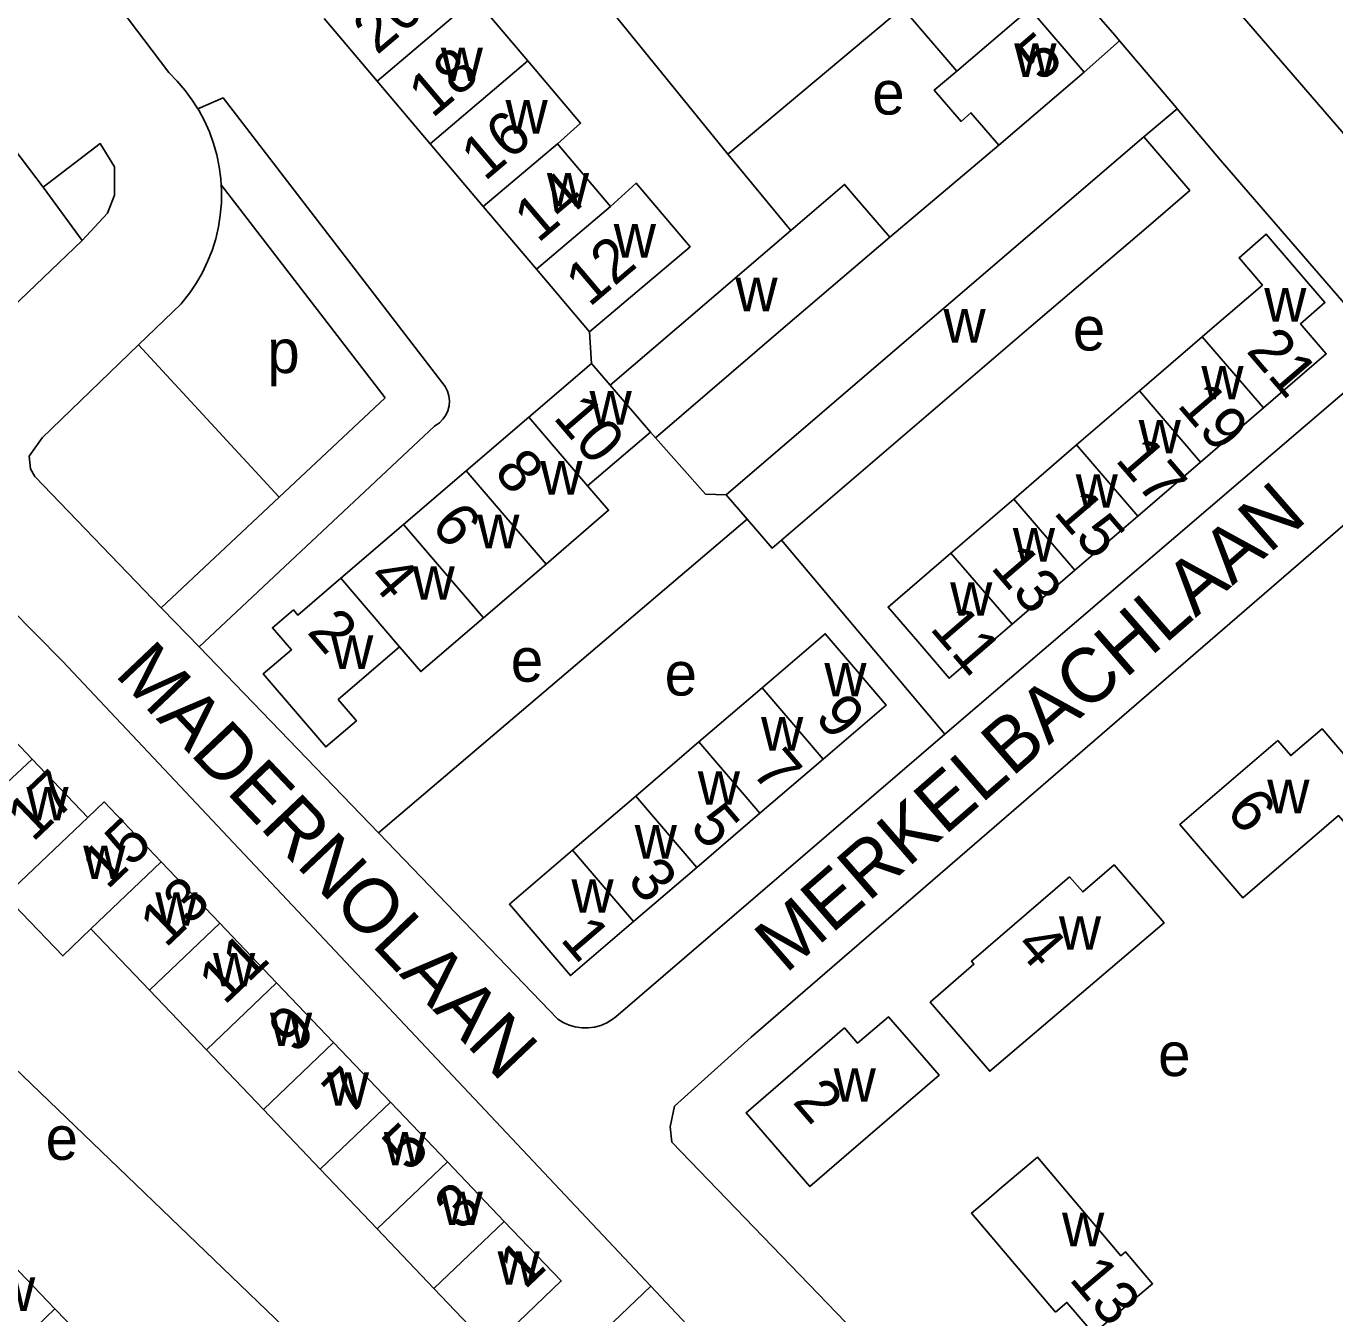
# Model space of a CAD drawing. Extents: x 158848 to 160613, y 385889 to 387762.
# Drawn here: x 160005.9 to 160125.8, y 386409.7 to 386527.7 of the extents above; entities that cross this region are included whole.
import ezdxf

# ---------------------------------------------------------------- set-up
doc = ezdxf.new("R2010")
doc.units = 0
for name, color, linetype in [('BLT_Basislijn', 7, 'Continuous'), ('BLT_Bebouwing', 7, 'Continuous'), ('BLT_Centroide', 7, 'Continuous'), ('BLT_Huisnummer', 7, 'Continuous'), ('BLT_Huisnummer_ tussenligend', 7, 'Continuous'), ('BLT_Onderverdeling_panden', 7, 'Continuous'), ('BLT_Straatnaam', 7, 'Continuous')]:
    doc.layers.add(name, color=color, linetype=linetype)

msp = doc.modelspace()

# ---------------------------------------------------------------- linework, layer by layer
at = {"layer": 'BLT_Basislijn'}
for p, q in [((160018.93, 386523.43), (160006.23, 386540.3)), ((160070.18, 386515.95), (160086.18, 386529.36)), ((160102.84, 386523.47), (160106.06, 386526.36)), ((160111.36, 386520.11), (160108.31, 386517.53)), ((160007.42, 386512.92), (160003.27, 386518.36)), ((160085.01, 386508.36), (160095.01, 386516.77)), ((160070.18, 386515.95), (160075.94, 386508.96)), ((160038.76, 386493.62), (160023.73, 386513.15)), ((160007.42, 386512.92), (160010.99, 386508.05)), ((160010.99, 386508.05), (159994.52, 386492.32)), ((160057.68, 386496.77), (160057.5, 386499.67)), ((160016.16, 386498.47), (160029.05, 386484.51)), ((160038.76, 386493.62), (160029.05, 386484.51)), ((160043.3, 386491.02), (160021.72, 386470.78)), ((160029.05, 386484.51), (160018.24, 386474.37)), ((160038.16, 386453.74), (160071.95, 386482.5)), ((160075.09, 386480.58), (160090.05, 386462.8)), ((160018.24, 386474.37), (160018.35, 386474.25)), ((160021.72, 386470.78), (160018.35, 386474.25)), ((160038.16, 386453.74), (160021.72, 386470.78)), ((160059.91, 386436.87), (160090.05, 386462.8)), ((160038.16, 386453.74), (160054.58, 386436.66)), ((160001.18, 386435.67), (160041.38, 386397.03)), ((160063.11, 386412.2), (160048.57, 386398.28))]:
    msp.add_line(p, q, dxfattribs=at)
for points in [[(160120.89, 386570.12), (160101.88, 386553.46), (160100.45, 386551.77), (160100.03, 386549.96), (160100.67, 386547.91), (160133.83, 386509.51)], [(160050.78, 386539.46), (160051.37, 386539.12), (160070.18, 386515.95)], [(160096.06, 386537.88), (160105.65, 386526.85), (160106.06, 386526.36)], [(160111.36, 386520.11), (160111.3, 386520.19), (160106.06, 386526.36)], [(160018.93, 386523.43), (160019.71, 386522.65), (160020.43, 386521.8), (160021.08, 386520.91), (160021.59, 386520.11)], [(160044.28, 386494.65), (160023.91, 386521.11), (160021.59, 386520.11)], [(160021.59, 386520.11), (160021.68, 386519.98), (160022.2, 386519), (160022.65, 386517.99), (160023.03, 386516.94), (160023.33, 386515.88), (160023.55, 386514.79), (160023.7, 386513.69), (160023.73, 386513.15)], [(160090.05, 386462.8), (160129.22, 386496.31), (160129.31, 386498.66), (160128.99, 386499.61), (160115.32, 386515.4), (160111.36, 386520.11)], [(160010.99, 386508.05), (160013.3, 386510.55), (160013.97, 386512.2), (160013.97, 386514.8), (160012.65, 386516.93), (160007.42, 386512.92)], [(160023.73, 386513.15), (160023.76, 386512.59), (160023.75, 386511.48), (160023.65, 386510.37), (160023.48, 386509.28), (160023.23, 386508.2), (160022.9, 386507.14), (160022.49, 386506.11), (160022.01, 386505.11), (160021.46, 386504.15), (160020.85, 386503.23), (160020.16, 386502.35), (160020.06, 386502.23)], [(160020.06, 386502.23), (160016.16, 386498.47)], [(160016.16, 386498.47), (160007.34, 386489.96), (160006.14, 386488.28), (160006.25, 386487.11), (160006.65, 386486.42), (160018.24, 386474.37)], [(160044.28, 386494.65), (160044.48, 386494.23), (160044.61, 386493.79), (160044.65, 386493.34), (160044.62, 386492.88), (160044.5, 386492.44), (160044.32, 386492.03), (160044.06, 386491.65), (160043.74, 386491.32), (160043.3, 386491.02)], [(160063.53, 386489.95), (160068.13, 386484.8), (160070.03, 386484.74)], [(160083.46, 386406.29), (160065.04, 386425.4), (160064.88, 386426.78), (160065.3, 386428.7), (160072.32, 386435), (160133.52, 386487.91), (160134.87, 386488.67), (160137.1, 386488.79), (160139.96, 386487.11), (160181.86, 386438.35)], [(159975.08, 386460.67), (159994.08, 386479.01), (159996.09, 386479.96), (159998.22, 386479.8), (159999.47, 386479.28), (160009.19, 386469.49), (160063.11, 386412.2)], [(160054.58, 386436.66), (160055.09, 386436.36), (160055.63, 386436.12), (160056.19, 386435.95), (160056.78, 386435.87), (160057.37, 386435.86), (160057.95, 386435.94), (160058.52, 386436.09), (160059.07, 386436.32), (160059.58, 386436.62), (160059.91, 386436.87)], [(160021.79, 386371.56), (160039.4, 386353.42), (160041.49, 386352.9), (160042.58, 386353.01), (160045.16, 386354.66), (160053.07, 386361.02), (160074.23, 386378.29), (160083.27, 386386.2), (160084.09, 386387.66), (160083.81, 386390.16), (160063.11, 386412.2)]]:
    msp.add_lwpolyline(points, dxfattribs=at)
at = {"layer": 'BLT_Bebouwing'}
for p, q in [((160091.15, 386523.55), (160086.18, 386529.36)), ((160102.84, 386523.47), (160097.86, 386529.29)), ((160038.03, 386522.65), (160033.16, 386528.39)), ((160042.9, 386516.9), (160038.03, 386522.65)), ((160095.01, 386516.77), (160102.84, 386523.47)), ((160047.76, 386511.16), (160042.9, 386516.9)), ((160059.42, 386511.17), (160054.55, 386516.91)), ((160052.63, 386505.41), (160047.76, 386511.16)), ((160057.5, 386499.67), (160052.63, 386505.41)), ((160107.9, 386494.25), (160113.66, 386499.21)), ((160057.68, 386496.77), (160051.92, 386491.84)), ((160059.39, 386494.78), (160057.68, 386496.77)), ((160102.14, 386489.3), (160107.9, 386494.25)), ((160113.51, 386487.73), (160119.27, 386492.69)), ((160051.92, 386491.84), (160046.18, 386486.93)), ((160057.31, 386485.54), (160063.08, 386490.47)), ((160063.08, 386490.47), (160063.53, 386489.95)), ((160096.38, 386484.34), (160102.14, 386489.3)), ((160046.18, 386486.93), (160040.44, 386482.01)), ((160107.75, 386482.78), (160113.51, 386487.73)), ((160070.03, 386484.74), (160071.95, 386482.5)), ((160090.62, 386479.39), (160096.38, 386484.34)), ((160040.44, 386482.01), (160034.69, 386477.09)), ((160101.99, 386477.82), (160107.75, 386482.78)), ((160047.77, 386473.45), (160053.51, 386478.38)), ((160096.23, 386472.87), (160101.99, 386477.82)), ((160067.53, 386462.07), (160073.32, 386467.03)), ((160006.41, 386460.5), (160001.14, 386466.02)), ((160061.74, 386457.11), (160067.53, 386462.07)), ((160011.51, 386455.15), (160006.41, 386460.5)), ((160073.12, 386455.54), (160078.91, 386460.49)), ((160055.95, 386452.15), (160061.74, 386457.11)), ((160067.33, 386450.58), (160073.12, 386455.54)), ((160023.6, 386445.46), (160018.23, 386451.09)), ((160061.54, 386445.62), (160067.33, 386450.58)), ((160017.16, 386439.32), (160011.8, 386444.94)), ((160028.82, 386440), (160023.6, 386445.46)), ((160034.03, 386434.53), (160028.82, 386440)), ((160022.38, 386433.85), (160017.16, 386439.32)), ((160027.6, 386428.39), (160022.38, 386433.85)), ((160039.25, 386429.06), (160034.03, 386434.53)), ((160044.47, 386423.59), (160039.25, 386429.06)), ((160032.81, 386422.92), (160027.6, 386428.39)), ((160049.68, 386418.12), (160044.47, 386423.59)), ((160038.03, 386417.45), (160032.81, 386422.92)), ((160043.24, 386411.98), (160038.03, 386417.45)), ((160003.25, 386415.55), (160008.5, 386410.11)), ((160008.5, 386410.11), (160013.75, 386404.68))]:
    msp.add_line(p, q, dxfattribs=at)
for points in [[(160051.83, 386524.52), (160046.94, 386530.29), (160044.82, 386528.4)], [(160054.55, 386516.91), (160056.68, 386518.8), (160051.83, 386524.52)], [(160095.01, 386516.77), (160092.46, 386519.75), (160091.55, 386518.96), (160089.09, 386521.83), (160091.15, 386523.55)], [(160108.31, 386517.53), (160087.84, 386500), (160070.03, 386484.74)], [(160108.31, 386517.53), (160112.51, 386512.63), (160108.72, 386509.37), (160097.77, 386500), (160075.09, 386480.58)], [(160059.42, 386511.17), (160061.77, 386513.3), (160066.71, 386507.47), (160060.87, 386502.52), (160057.5, 386499.67)], [(160075.94, 386508.96), (160080.88, 386513.18), (160081.76, 386512.15), (160085.01, 386508.36)], [(160075.94, 386508.96), (160065.49, 386500), (160059.39, 386494.78)], [(160063.53, 386489.95), (160075.26, 386500), (160085.01, 386508.36)], [(160113.66, 386499.21), (160114.58, 386500), (160119.18, 386503.96), (160117.03, 386506.46), (160119.52, 386508.61), (160124.9, 386502.35), (160122.65, 386500.4), (160123, 386500), (160125.03, 386497.64), (160119.27, 386492.69)], [(160053.51, 386478.38), (160059.24, 386483.32), (160057.31, 386485.54)], [(160071.95, 386482.5), (160073.28, 386480.95), (160074.23, 386479.84), (160075.09, 386480.58)], [(160096.23, 386472.87), (160090.46, 386467.92), (160087.58, 386471.27), (160084.86, 386474.44), (160090.62, 386479.39)], [(160040.09, 386470.79), (160034.47, 386465.96), (160036.13, 386464.02), (160033.32, 386461.62), (160027.58, 386468.31), (160030.17, 386470.52), (160028.43, 386472.54), (160030.35, 386474.18), (160030.75, 386473.71), (160034.69, 386477.09)], [(160040.09, 386470.79), (160042.03, 386468.52), (160047.77, 386473.45)], [(160073.32, 386467.03), (160079.11, 386471.99), (160081.87, 386468.76), (160084.7, 386465.45), (160078.91, 386460.49)], [(160120.59, 386462.21), (160121.77, 386460.83), (160124.64, 386463.29), (160127.89, 386459.5), (160131.35, 386455.46), (160128.29, 386452.83), (160126.15, 386455.32), (160117.37, 386447.79), (160114.44, 386451.21), (160111.61, 386454.52), (160120.59, 386462.21)], [(160018.23, 386451.09), (160013, 386456.57), (160011.51, 386455.15)], [(160055.95, 386452.15), (160054.24, 386450.7), (160050.15, 386447.2), (160055.75, 386440.66), (160061.54, 386445.62)], [(160101.5, 386449.71), (160102.7, 386448.33), (160105.57, 386450.8), (160108.84, 386447.02), (160110.16, 386445.48), (160094.18, 386431.89), (160088.71, 386438.22), (160092.73, 386441.69), (160092.51, 386441.97), (160101.5, 386449.71)], [(160011.8, 386444.94), (160009.21, 386442.46), (160003.96, 386447.95), (160005.34, 386449.27)], [(160081.48, 386424.58), (160089.53, 386431.52), (160088.16, 386433.11), (160084.9, 386436.89), (160082.07, 386434.45), (160080.86, 386435.86), (160071.85, 386428.08), (160077.7, 386421.31), (160081.48, 386424.58)], [(160100.21, 386409.81), (160101.26, 386410.7), (160103.69, 386407.84), (160109.1, 386412.41), (160106.63, 386415.33), (160106.21, 386414.98), (160098.57, 386424.01), (160095.48, 386421.4), (160093.68, 386419.87), (160092.52, 386418.89), (160100.21, 386409.81)], [(160049.68, 386418.12), (160054.9, 386412.66), (160051.71, 386409.61), (160048.46, 386406.51), (160043.24, 386411.98)]]:
    msp.add_lwpolyline(points, dxfattribs=at)
at = {"layer": 'BLT_Onderverdeling_panden'}
for p, q in [((160097.86, 386529.29), (160091.15, 386523.55)), ((160038.03, 386522.65), (160044.82, 386528.4)), ((160042.9, 386516.9), (160051.83, 386524.52)), ((160047.76, 386511.16), (160054.55, 386516.91)), ((160052.63, 386505.41), (160059.42, 386511.17)), ((160119.27, 386492.69), (160113.66, 386499.21)), ((160059.39, 386494.78), (160063.08, 386490.47)), ((160113.51, 386487.73), (160107.9, 386494.25)), ((160057.31, 386485.54), (160051.92, 386491.84)), ((160107.75, 386482.78), (160102.14, 386489.3)), ((160053.51, 386478.38), (160046.18, 386486.93)), ((160101.99, 386477.82), (160096.38, 386484.34)), ((160047.77, 386473.45), (160040.44, 386482.01)), ((160096.23, 386472.87), (160090.62, 386479.39)), ((160040.09, 386470.79), (160034.69, 386477.09)), ((160078.91, 386460.49), (160073.32, 386467.03)), ((160073.12, 386455.54), (160067.53, 386462.07)), ((160000.16, 386454.69), (160006.41, 386460.5)), ((160067.33, 386450.58), (160061.74, 386457.11)), ((160011.51, 386455.15), (160005.34, 386449.27)), ((160061.54, 386445.62), (160055.95, 386452.15)), ((160011.8, 386444.94), (160018.23, 386451.09)), ((160017.16, 386439.32), (160023.6, 386445.46)), ((160022.38, 386433.85), (160028.82, 386440)), ((160027.6, 386428.39), (160034.03, 386434.53)), ((160032.81, 386422.92), (160039.25, 386429.06)), ((160038.03, 386417.45), (160044.47, 386423.59)), ((160043.24, 386411.98), (160049.68, 386418.12)), ((160002.39, 386404.27), (160008.5, 386410.11))]:
    msp.add_line(p, q, dxfattribs=at)

# ---------------------------------------------------------------- texts
at = {"layer": 'BLT_Centroide'}
for s, p in [('w', (160043.86, 386522.66)), ('w', (160096.43, 386523.03)), ('e', (160083.41, 386519.59)), ('w', (160049.8, 386517.84)), ('w', (160053.59, 386511.16)), ('w', (160059.72, 386506.47)), ('w', (160070.87, 386501.56)), ('w', (160119.34, 386500.61)), ('w', (160089.94, 386498.69)), ('e', (160101.8, 386497.96)), ('p', (160027.96, 386495.89)), ('w', (160113.58, 386493.48)), ('w', (160057.5, 386491.16)), ('w', (160107.83, 386488.52)), ('w', (160052.98, 386484.75)), ('w', (160102.06, 386483.55)), ('w', (160047.2, 386479.83)), ('w', (160096.3, 386478.61)), ('w', (160041.28, 386475.11)), ('w', (160090.55, 386473.64)), ('w', (160033.81, 386468.77)), ('e', (160050.28, 386467.6)), ('e', (160064.38, 386466.33)), ('w', (160079.02, 386466.25)), ('w', (160073.22, 386461.28)), ('w', (160067.42, 386456.31)), ('w', (160005.88, 386454.88)), ('w', (160119.62, 386455.53)), ('w', (160061.64, 386451.38)), ('w', (160011.09, 386449.5)), ('w', (160055.84, 386446.41)), ('w', (160017.7, 386445.22)), ('w', (160100.52, 386443.03)), ('w', (160022.99, 386439.66)), ('w', (160028.21, 386434.19)), ('e', (160109.61, 386431.45)), ('w', (160033.42, 386428.72)), ('w', (160079.88, 386429.09)), ('e', (160007.64, 386423.77)), ('w', (160038.64, 386423.25)), ('w', (160043.85, 386417.78)), ('w', (160100.81, 386415.84)), ('w', (160049.07, 386412.31)), ('w', (160002.82, 386409.91))]:
    msp.add_text(s, height=4, dxfattribs=at).set_placement(p)
at = {"layer": 'BLT_Huisnummer'}
for s, rotation, p in [('20', 40.2776, (160038.01, 386524.99)), ('5', 40.5773, (160098.86, 386522.47)), ('16', 40.2776, (160047.89, 386513.4)), ('12', 40.2776, (160057.48, 386501.87)), ('21', 310.6996, (160117.61, 386497.89)), ('10', 310.5826, (160054.08, 386491.79)), ('15', 310.6996, (160099.95, 386483.07)), ('6', 310.5781, (160042.85, 386481.86)), ('2', 310.5826, (160031.52, 386472.13)), ('11', 310.6997, (160088.6, 386472.45)), ('9', 310.5673, (160078.06, 386464.3)), ('17', 43.649, (160006.47, 386452.82)), ('6', 310.8221, (160115.71, 386455.67)), ('5', 310.5673, (160066.59, 386454.25)), ('13', 43.649, (160018.64, 386443.11)), ('1', 310.5724, (160054.73, 386443.95)), ('4', 310.8221, (160096.41, 386443.29)), ('9', 43.649, (160030.45, 386433.38)), ('2', 310.8221, (160076.02, 386429.06)), ('5', 43.649, (160040.88, 386422.55)), ('1', 43.649, (160051.55, 386411.78)), ('13', 310.2508, (160101.37, 386412.81))]:
    msp.add_text(s, height=4, rotation=rotation, dxfattribs=at).set_placement(p)
at = {"layer": 'BLT_Huisnummer_ tussenligend'}
for s, rotation, p in [('18', 40.2776, (160043.08, 386519.18)), ('14', 40.2776, (160052.77, 386507.74)), ('19', 310.6996, (160111.27, 386492.92)), ('17', 310.6996, (160105.6, 386487.9)), ('8', 310.5781, (160048.63, 386486.77)), ('13', 310.6997, (160094.18, 386478.04)), ('4', 310.5826, (160037.07, 386477.06)), ('7', 310.5673, (160072.25, 386459.29)), ('15', 43.649, (160013.3, 386448.46)), ('3', 310.5724, (160060.85, 386449.32)), ('11', 43.649, (160024.03, 386437.87)), ('7', 43.649, (160035.42, 386427.67)), ('3', 43.649, (160045.67, 386417.13))]:
    msp.add_text(s, height=4, rotation=rotation, dxfattribs=at).set_placement(p)
at = {"layer": 'BLT_Straatnaam'}
for s, rotation, p in [('MERKELBACHLAAN', 41.0024, (160075.47, 386440.76)), ('MADERNOLAAN', 313.5461, (160013.88, 386468.23))]:
    msp.add_text(s, height=5, rotation=rotation, dxfattribs=at).set_placement(p)

doc.saveas('drawing.dxf')
